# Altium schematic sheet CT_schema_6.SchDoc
size 582 x 363 mm
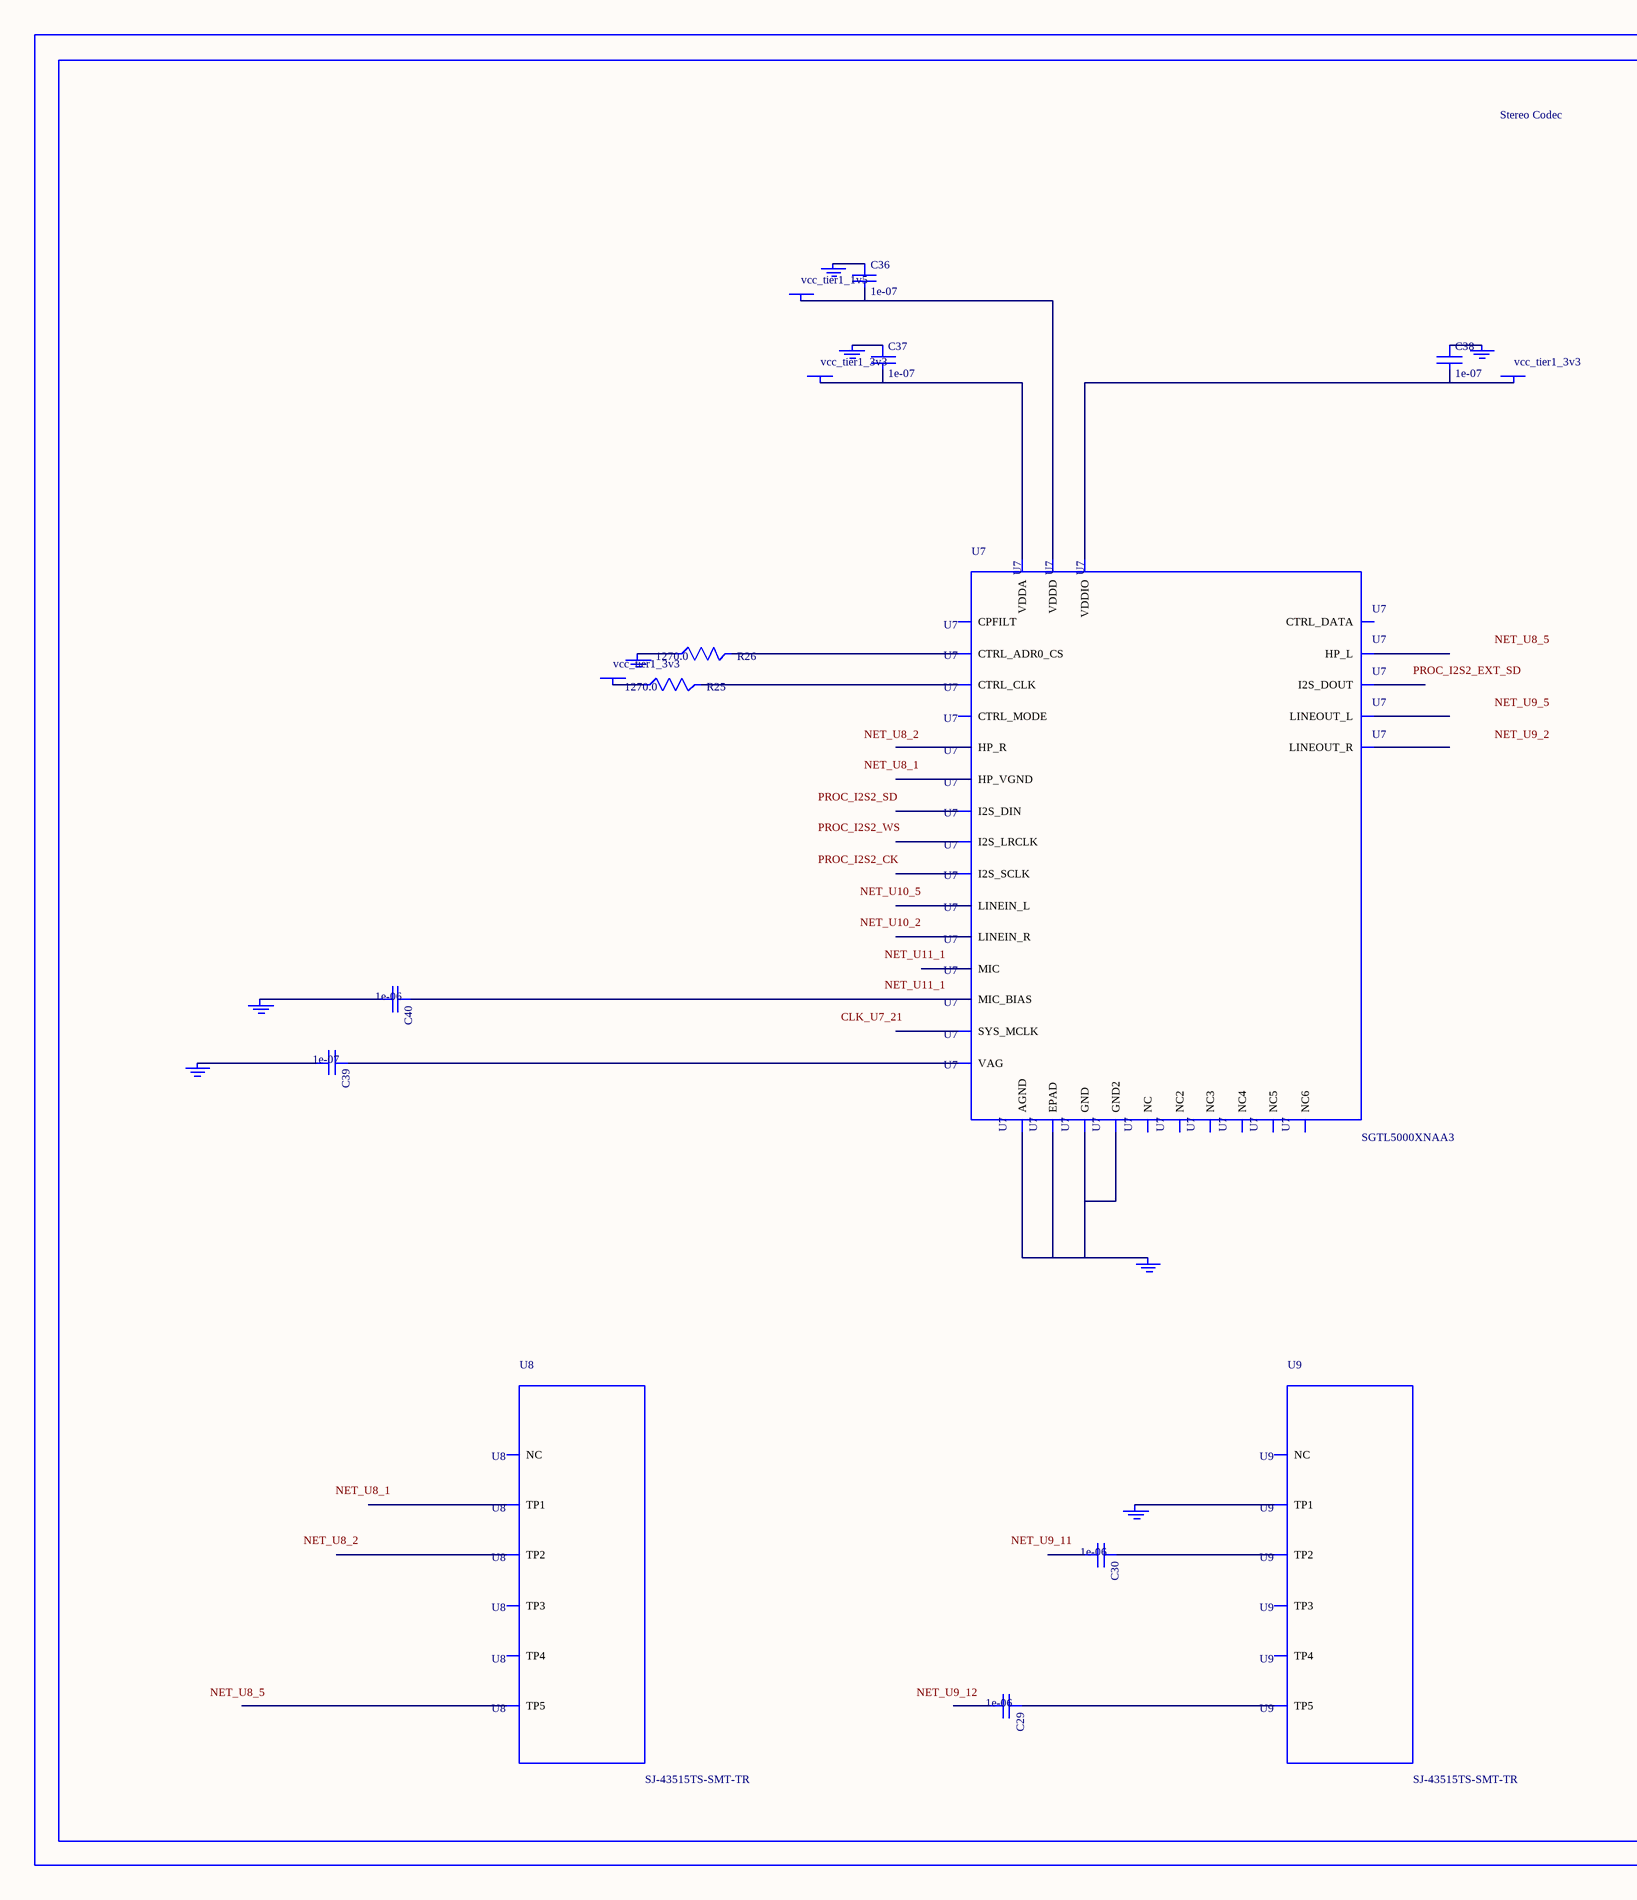
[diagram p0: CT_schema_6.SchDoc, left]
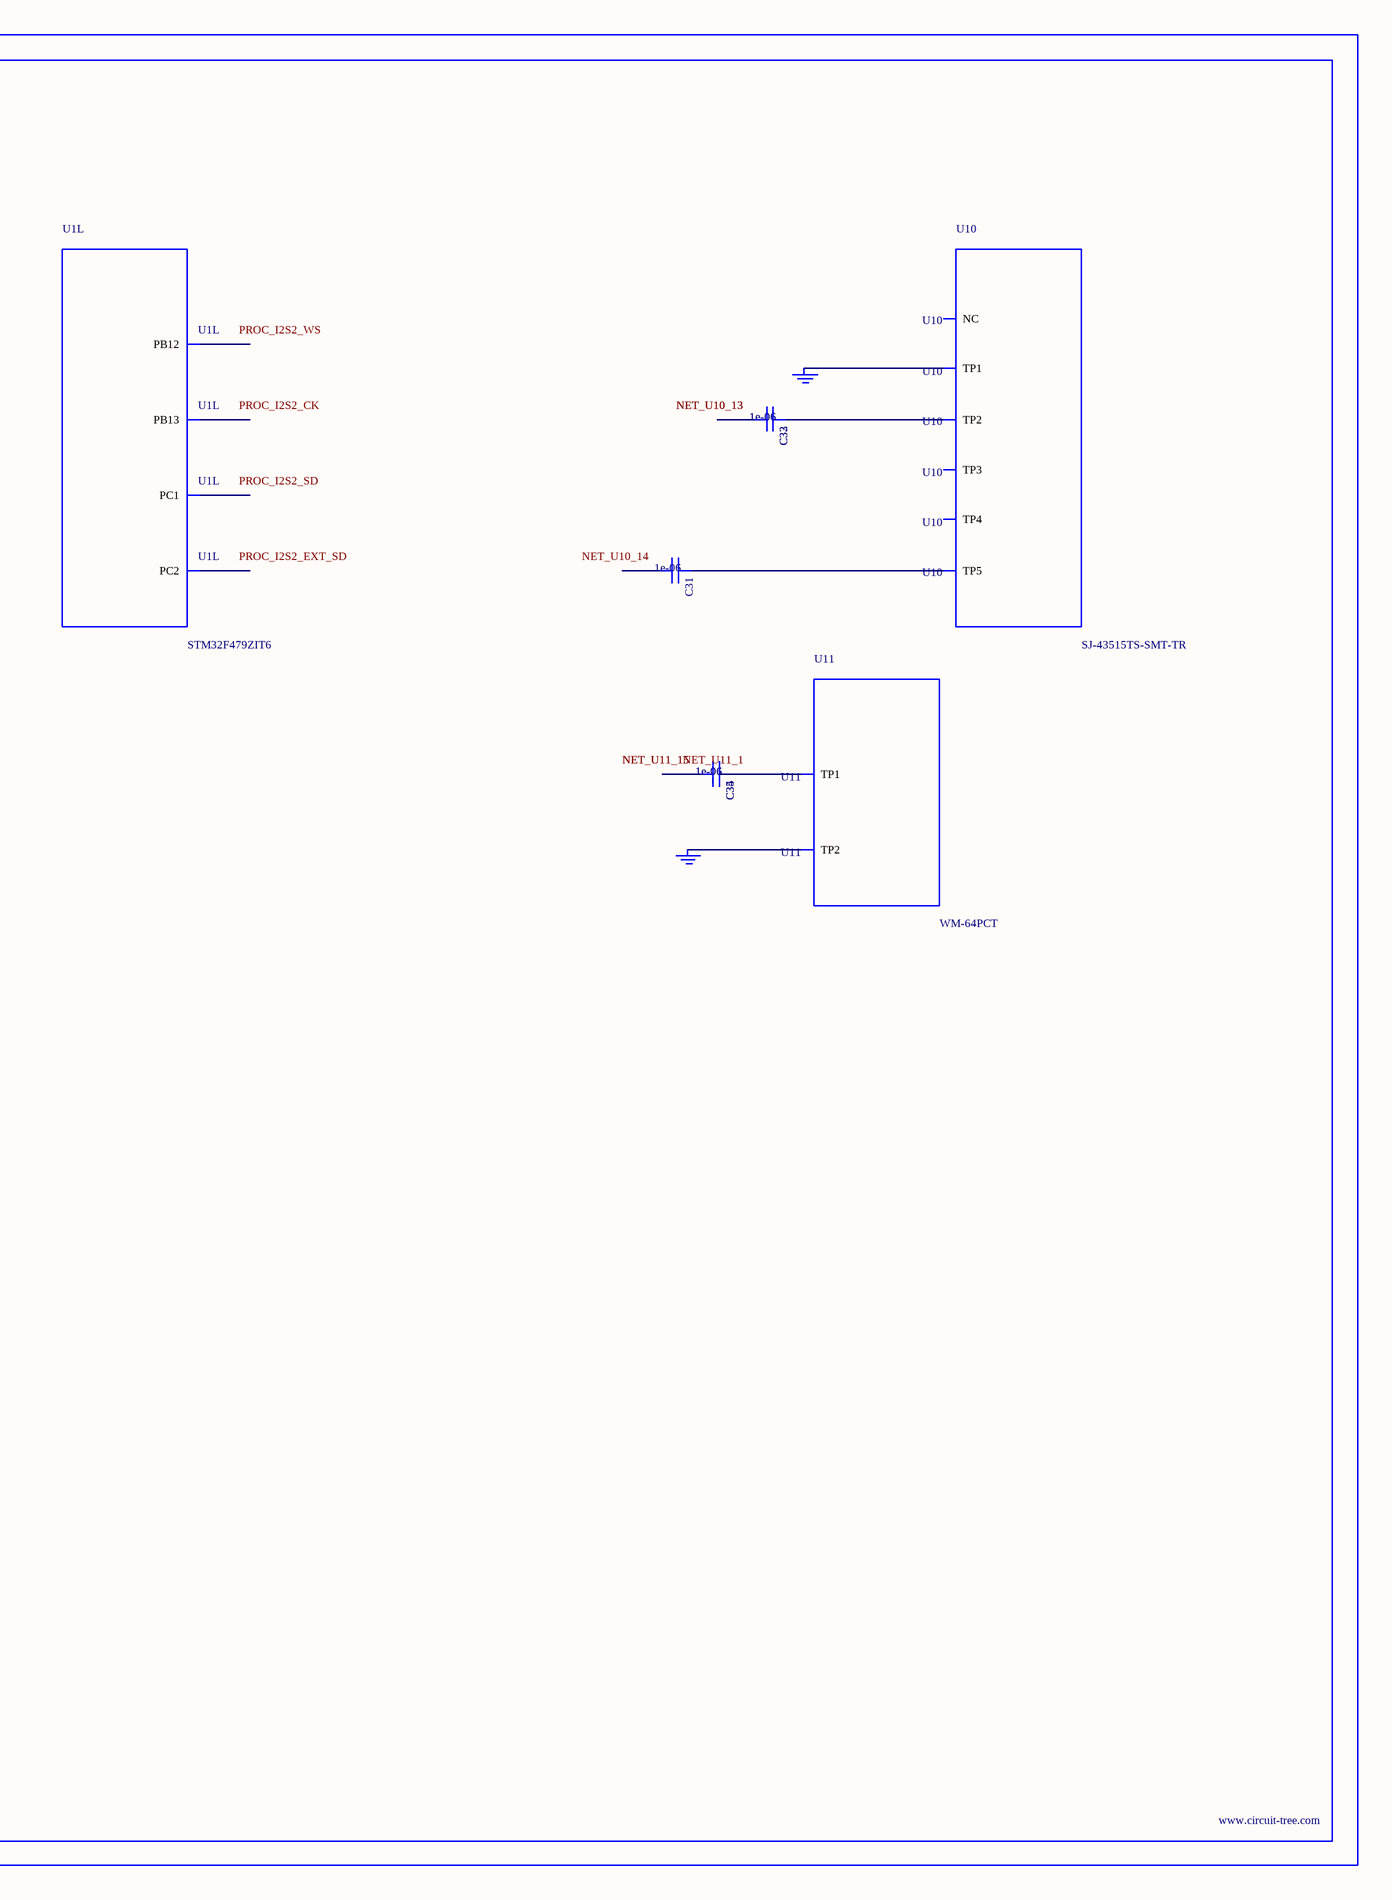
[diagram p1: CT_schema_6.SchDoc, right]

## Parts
BORDER5  (no value)
C29  1e-06  [C0603]
C30  1e-06  [C0603]
C31  1e-06  [C0603]
C32  1e-06  [C0603]
C33  1e-06  [C0603]
C34  1e-06  [C0603]
C35  1e-06  [C0603]
C36  1e-07  [C0402]
C37  1e-07  [C0402]
C38  1e-07  [C0402]
C39  1e-07  [C0402]
C40  1e-06  [C0603]
GND_INSTANCE_5_0  (no value)
GND_INSTANCE_5_1  (no value)
GND_INSTANCE_5_2  (no value)
GND_INSTANCE_5_3  (no value)
GND_INSTANCE_5_4  (no value)
GND_INSTANCE_5_5  (no value)
GND_INSTANCE_5_6  (no value)
GND_INSTANCE_5_7  (no value)
GND_INSTANCE_5_8  (no value)
GND_INSTANCE_5_9  (no value)
GND_INSTANCE_5_10  (no value)
POWER_INSTANCE_5_0  vcc_tier1_3v3
POWER_INSTANCE_5_1  vcc_tier1_3v3
POWER_INSTANCE_5_2  vcc_tier1_3v3
POWER_INSTANCE_5_3  vcc_tier1_1v5
R25  1270.0  [R0603]
R26  1270.0  [R0603]
U1  STM32F479ZIT6  [LQFP144]  (part L of 13)
U7  SGTL5000XNAA3  [QFN-32]
U8  SJ-43515TS-SMT-TR  [SJ-43515TS-SMT-TR]
U9  SJ-43515TS-SMT-TR  [SJ-43515TS-SMT-TR]
U10  SJ-43515TS-SMT-TR  [SJ-43515TS-SMT-TR]
U11  WM-64PCT  [WM-64PC]

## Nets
NetC29_1: C29.1 U9.5(TP5)
NetC30_1: C30.1 U9.2(TP2)
NetC31_1: C31.1 U10.5(TP5)
NetC32_1: C32.1 C33.1 U10.2(TP2)
NetC32_2: C32.2 C33.2
NetC34_1: C34.1 C35.1 U11.1(TP1)
NetC34_2: C34.2 C35.2
NetC36_1: C36.1 GND_INSTANCE_5_5.0(GND)
NetC36_2: C36.2 POWER_INSTANCE_5_3.0(PWR) U7.30(VDDD)
NetC37_1: C37.1 GND_INSTANCE_5_1.0(GND)
NetC37_2: C37.2 POWER_INSTANCE_5_0.0(PWR) U7.5(VDDA)
NetC38_1: C38.1 GND_INSTANCE_5_4.0(GND)
NetC38_2: C38.2 POWER_INSTANCE_5_1.0(PWR) U7.20(VDDIO)
NetC39_1: C39.1 U7.10(VAG)
NetC39_2: C39.2 GND_INSTANCE_5_2.0(GND)
NetC40_1: C40.1 U7.16(MIC_BIAS)
NetC40_2: C40.2 GND_INSTANCE_5_3.0(GND)
NetGND_INSTANCE_5_0_0: GND_INSTANCE_5_0.0(GND) U7.1(GND) U7.3(GND2) U7.7(AGND) U7.EXP(EPAD)
NetGND_INSTANCE_5_6_0: GND_INSTANCE_5_6.0(GND) R26.1
NetGND_INSTANCE_5_7_0: GND_INSTANCE_5_7.0(GND) U9.1(TP1)
NetGND_INSTANCE_5_8_0: GND_INSTANCE_5_8.0(GND) GND_INSTANCE_5_9.0(GND) U10.1(TP1)
NetGND_INSTANCE_5_10_0: GND_INSTANCE_5_10.0(GND) U11.2(TP2)
NetPOWER_INSTANCE_5_2_0: POWER_INSTANCE_5_2.0(PWR) R25.1
NetR25_2: R25.2 U7.29(CTRL_CLK)
NetR26_2: R26.2 U7.31(CTRL_ADR0_CS)

Not connected (* = marked no-connect by the designer): C29 2; C30 2; C31 2; U1 22(PC1) 23(PC2) 67(PB12) 68(PB13); U7 2(HP_R) 4(HP_VGND) 6(HP_L) 8(NC) 9(NC2) 11(LINEOUT_R) 12(LINEOUT_L) 13(LINEIN_R) 14(LINEIN_L) 15(MIC) 17(NC3) 18(CPFILT) 19(NC4) 21(SYS_MCLK) 22(NC5) 23(I2S_LRCLK) 24(I2S_SCLK) 25(I2S_DOUT) 26(I2S_DIN) 27(CTRL_DATA) 28(NC6) 32(CTRL_MODE); U8 1(TP1) 2(TP2) 3(TP3) 4(TP4) 5(TP5) 6(NC); U9 3(TP3) 4(TP4) 6(NC); U10 3(TP3) 4(TP4) 6(NC)

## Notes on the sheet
- Labels drawn without touching a wire or pin: CLK_U7_21, NET_U8_1, NET_U8_2, NET_U8_5, NET_U9_2, NET_U9_5, NET_U9_11, NET_U9_12, NET_U10_2, NET_U10_5, NET_U10_14, NET_U11_1, PROC_I2S2_CK, PROC_I2S2_EXT_SD, PROC_I2S2_SD, PROC_I2S2_WS

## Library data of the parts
BORDER5 = BORDER_PAGE5
C29-C35 C40 = C0603C105K3RACTU
C36-C39 = C0402C104K3RACTU
GND_INSTANCE_5_0-GND_INSTANCE_5_10 = GND
POWER_INSTANCE_5_0-POWER_INSTANCE_5_3 = PWR
R25 R26 = RC0603FR-071K27L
